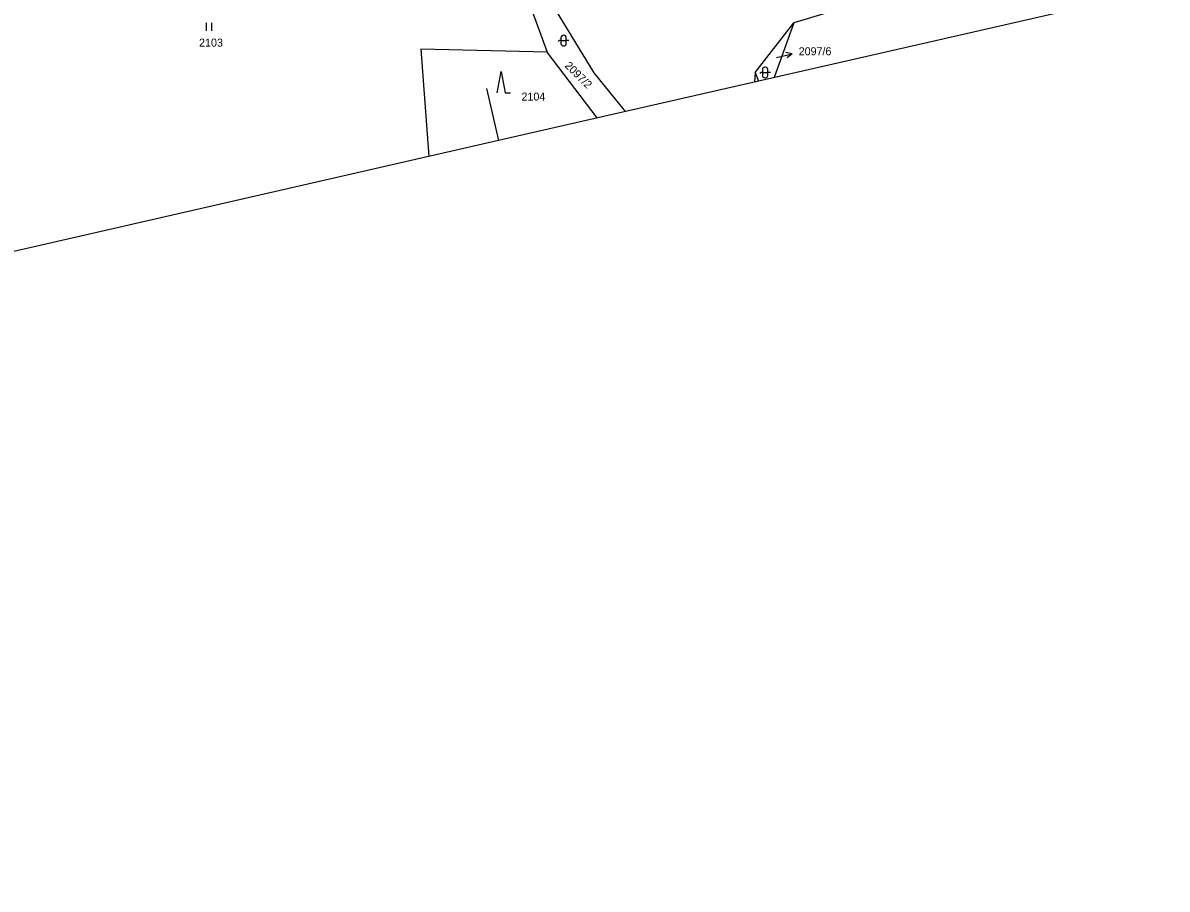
# Model space of a CAD drawing. Extents: x -805730 to -804640, y -1150889 to -1150366.
# Drawn here: x -805139 to -804924.5, y -1150889.4 to -1150727 of the extents above; entities that cross this region are included whole.
import ezdxf

# ---------------------------------------------------------------- set-up
doc = ezdxf.new("R2010")
doc.units = 0
for name, color, linetype in [('Default', 7, 'Continuous'), ('formát', 7, 'Continuous'), ('kn_celek - Cisla parcel pomocna', 7, 'Continuous'), ('kn_celek - Cisla pozemkovych parcel', 7, 'Continuous'), ('kn_celek - Hranice parcel', 7, 'Continuous'), ('kn_celek - Znacky kultur', 7, 'Continuous')]:
    doc.layers.add(name, color=color, linetype=linetype)

# ---------------------------------------------------------------- blocks, each defined once
blk = doc.blocks.new('306')
at = {"layer": 'Default'}
for p, q in [((-5.2, 0), (-5.2, 15)), ((4.8, 0), (4.8, 15))]:
    blk.add_line(p, q, dxfattribs=at)
blk = doc.blocks.new('308')
at = {"layer": 'Default'}
for p, q in [((-7.5, 0.2), (0, 40.2)), ((0, 40.2), (7.5, 0.2)), ((7.5, 0.2), (17.5, 0.2))]:
    blk.add_line(p, q, dxfattribs=at)
blk = doc.blocks.new('316')
at = {"layer": 'Default'}
for p, q in [((-8.3, 10), (-10, 8.1)), ((-5, 10), (-8.3, 10)), ((-5, 15.5), (-5, 4.5)), ((-5, 10), (5, 10)), ((0.5, 20), (-0.5, 20)), ((-0.5, 0), (0.5, 0)), ((5, 4.5), (5, 15.5)), ((10, 10), (5, 10))]:
    blk.add_line(p, q, dxfattribs=at)
for centre, start, end in [((-0.5, 15.5), 90, 180), ((-0.5, 4.5), 180, 270), ((0.5, 15.5), 0, 90), ((0.5, 4.5), 270, 0)]:
    blk.add_arc(centre, 4.5, start, end, dxfattribs=at)
blk = doc.blocks.new('Z61')
at = {"layer": 'Default'}
for p, q in [((0, 0), (30, 0)), ((30, 0), (19.2, 5.3)), ((30, 0), (19.2, -5.3))]:
    blk.add_line(p, q, dxfattribs=at)

msp = doc.modelspace()

# ---------------------------------------------------------------- linework, layer by layer
at = {"layer": 'formát'}
for p, q in [((-804845.15, -1150702.29), (-805049.87, -1150749.08)), ((-805052.1, -1150739.33), (-805049.87, -1150749.08)), ((-805052.1, -1150739.33), (-805049.87, -1150749.08)), ((-805049.87, -1150749.08), (-805664.04, -1150889.45))]:
    msp.add_line(p, q, dxfattribs=at)
at = {"layer": 'kn_celek - Hranice parcel'}
for p, q in [((-805050.29, -1150706.27), (-805040.7, -1150732.48)), ((-804969.06, -1150719.29), (-804994.48, -1150727.02)), ((-805041.32, -1150721.06), (-805031.98, -1150736.39)), ((-805001.73, -1150736.29), (-804994.48, -1150727.02)), ((-804994.48, -1150727.02), (-804998.15, -1150737.26)), ((-805040.7, -1150732.48), (-805064.39, -1150731.96)), ((-805064.39, -1150731.96), (-805062.94, -1150752.07)), ((-805031.34, -1150744.84), (-805040.7, -1150732.48)), ((-805031.98, -1150736.39), (-805026.09, -1150743.64)), ((-805001.73, -1150736.29), (-805001.84, -1150738.1)), ((-805001.73, -1150736.29), (-805001.13, -1150737.94))]:
    msp.add_line(p, q, dxfattribs=at)

# ---------------------------------------------------------------- block references
at = {"layer": 'kn_celek - Cisla parcel pomocna', "xscale": 0.1, "yscale": 0.09999999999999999, "rotation": 12.518280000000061}
msp.add_blockref('Z61', (-804997.75, -1150733.47), dxfattribs=at)
at = {"layer": 'kn_celek - Znacky kultur', "xscale": 0.1, "yscale": 0.10000000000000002}
for name, p in [('306', (-805104.07, -1150728.52)), ('316', (-805037.64, -1150731.33)), ('316', (-804999.87, -1150737.31)), ('308', (-805049.34, -1150740.14))]:
    msp.add_blockref(name, p, dxfattribs=at)

# ---------------------------------------------------------------- texts
at = {"layer": 'kn_celek - Cisla parcel pomocna'}
msp.add_text('2097/6', height=1.5, dxfattribs=at).set_placement((-804993.58, -1150733.08))
at = {"layer": 'kn_celek - Cisla pozemkovych parcel'}
for s, p in [('2103', (-805105.98, -1150731.46)), ('2104', (-805045.54, -1150741.58))]:
    msp.add_text(s, height=1.5, dxfattribs=at).set_placement(p)
msp.add_text('2097/2', height=1.5, rotation=315.3136, dxfattribs=at).set_placement((-805037.56, -1150735.15))

doc.saveas('drawing.dxf')
